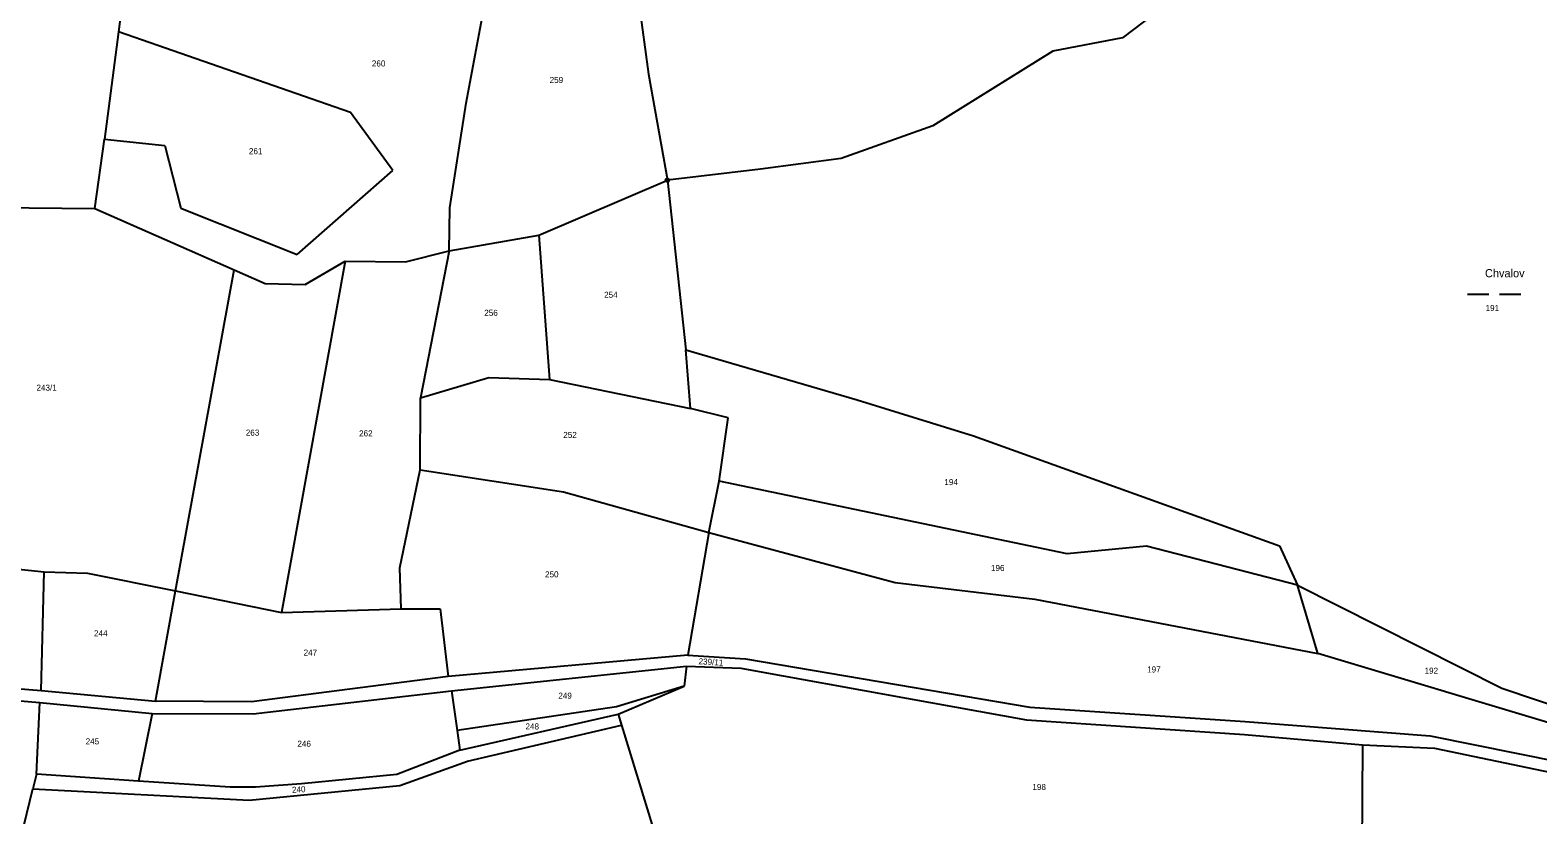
# Model space of a CAD drawing. Extents: x -794421 to -792735, y -1117671 to -1115559.
# Drawn here: x -794007.8 to -793585, y -1116101.2 to -1115881.2 of the extents above; entities that cross this region are included whole.
import ezdxf

# ---------------------------------------------------------------- set-up
doc = ezdxf.new("R2010")
doc.units = 0
for name, color, linetype in [('Vrstva 1', 7, 'Continuous'), ('Vrstva 14', 7, 'Continuous'), ('Vrstva 23', 7, 'Continuous'), ('Vrstva 28', 7, 'Continuous'), ('Vrstva 3', 7, 'Continuous'), ('Vrstva 44', 7, 'Continuous')]:
    doc.layers.add(name, color=color, linetype=linetype)

msp = doc.modelspace()

# ---------------------------------------------------------------- linework, layer by layer
at = {"layer": 'Vrstva 1'}
for p, q in [((-793981.74, -1115872.18), (-793982.97, -1115881.64)), ((-793885.49, -1115901.69), (-793881.05, -1115877.8)), ((-793982.97, -1115881.64), (-793986.9, -1115911.77)), ((-793917.95, -1115904.27), (-793982.97, -1115881.64)), ((-793906.06, -1115920.6), (-793917.95, -1115904.27)), ((-793890.06, -1115931.01), (-793885.49, -1115901.69)), ((-793989.67, -1115931.27), (-793986.9, -1115911.77)), ((-793986.9, -1115911.77), (-793969.98, -1115913.53)), ((-793969.98, -1115913.53), (-793965.54, -1115931.12)), ((-793932.88, -1115944.09), (-793906.06, -1115920.6)), ((-793865.09, -1115938.67), (-793829.08, -1115923.3)), ((-793829.08, -1115923.3), (-793823.91, -1115970.84)), ((-794038.38, -1115930.69), (-793989.67, -1115931.27)), ((-793989.67, -1115931.27), (-793950.58, -1115948.42)), ((-793965.54, -1115931.12), (-793932.88, -1115944.09)), ((-793890.28, -1115943.07), (-793890.06, -1115931.01)), ((-793890.28, -1115943.07), (-793865.09, -1115938.67)), ((-793865.09, -1115938.67), (-793862.1, -1115979.19)), ((-793919.41, -1115946.01), (-793937.25, -1116044.49)), ((-793930.65, -1115952.51), (-793919.41, -1115946.01)), ((-793919.41, -1115946.01), (-793902.53, -1115946.18)), ((-793902.53, -1115946.18), (-793890.28, -1115943.07)), ((-793890.28, -1115943.07), (-793898.31, -1115984.29)), ((-793967, -1116038.47), (-793950.58, -1115948.42)), ((-793950.58, -1115948.42), (-793941.85, -1115952.29)), ((-793941.85, -1115952.29), (-793930.65, -1115952.51)), ((-793823.91, -1115970.84), (-793775.82, -1115984.83)), ((-793822.57, -1115987.33), (-793823.91, -1115970.84)), ((-793898.31, -1115984.29), (-793879.15, -1115978.61)), ((-793879.15, -1115978.61), (-793862.1, -1115979.19)), ((-793862.1, -1115979.19), (-793822.57, -1115987.33)), ((-793898.42, -1116004.52), (-793898.31, -1115984.29)), ((-793775.82, -1115984.83), (-793743.24, -1115995)), ((-793812.03, -1115989.92), (-793822.57, -1115987.33)), ((-793814.59, -1116007.68), (-793812.03, -1115989.92)), ((-793743.24, -1115995), (-793657.44, -1116025.77)), ((-793904.1, -1116032), (-793898.42, -1116004.52)), ((-793898.42, -1116004.52), (-793858.22, -1116010.63)), ((-793817.49, -1116022.11), (-793814.59, -1116007.68)), ((-793716.97, -1116028.03), (-793814.59, -1116007.68)), ((-793858.22, -1116010.63), (-793817.49, -1116022.11)), ((-793817.49, -1116022.11), (-793823.34, -1116056.5)), ((-793817.49, -1116022.11), (-793765.24, -1116036.11)), ((-794059.95, -1116027.16), (-794003.8, -1116033.12)), ((-793694.7, -1116025.87), (-793716.97, -1116028.03)), ((-793652.4, -1116036.86), (-793694.7, -1116025.87)), ((-793657.44, -1116025.77), (-793652.4, -1116036.86)), ((-794004.72, -1116066.36), (-794003.8, -1116033.12)), ((-794003.8, -1116033.12), (-793991.65, -1116033.5)), ((-793991.65, -1116033.5), (-793967, -1116038.47)), ((-793903.72, -1116043.46), (-793904.1, -1116032)), ((-793972.59, -1116069.35), (-793967, -1116038.47)), ((-793967, -1116038.47), (-793937.25, -1116044.49)), ((-793765.24, -1116036.11), (-793726.06, -1116040.78)), ((-793652.4, -1116036.86), (-793595.03, -1116065.71)), ((-793646.63, -1116056.03), (-793652.4, -1116036.86)), ((-793937.25, -1116044.49), (-793903.72, -1116043.46)), ((-793903.72, -1116043.46), (-793892.8, -1116043.52)), ((-793892.8, -1116043.52), (-793890.53, -1116062.48)), ((-793726.06, -1116040.78), (-793646.63, -1116056.03)), ((-793823.34, -1116056.5), (-793890.53, -1116062.48)), ((-793823.34, -1116056.5), (-793807.18, -1116057.49)), ((-793568.92, -1116079.35), (-793646.63, -1116056.03)), ((-793889.59, -1116066.45), (-793823.74, -1116059.52)), ((-793823.74, -1116059.52), (-793824.33, -1116065.19)), ((-793823.74, -1116059.52), (-793808.47, -1116060.15)), ((-793808.47, -1116060.15), (-793762.05, -1116068.49)), ((-793807.18, -1116057.49), (-793727.4, -1116071.06)), ((-794065.04, -1116064.56), (-794005.06, -1116069.79)), ((-794064.7, -1116061.44), (-794004.72, -1116066.36)), ((-793890.53, -1116062.48), (-793945.69, -1116069.57)), ((-793824.33, -1116065.19), (-793843.38, -1116070.92)), ((-793842.87, -1116072.97), (-793824.33, -1116065.19)), ((-794005.99, -1116089.87), (-794005.06, -1116069.79)), ((-794005.06, -1116069.79), (-793973.59, -1116072.85)), ((-794004.72, -1116066.36), (-793972.59, -1116069.35)), ((-793945.69, -1116069.57), (-793972.59, -1116069.35)), ((-793945.24, -1116072.9), (-793889.59, -1116066.45)), ((-793889.59, -1116066.45), (-793887.99, -1116077.56)), ((-793762.05, -1116068.49), (-793728.37, -1116074.65)), ((-793595.03, -1116065.71), (-793554.97, -1116079.2)), ((-793973.59, -1116072.85), (-793977.38, -1116091.77)), ((-793973.59, -1116072.85), (-793945.24, -1116072.9)), ((-793843.38, -1116070.92), (-793887.99, -1116077.56)), ((-793887.23, -1116083.12), (-793842.87, -1116072.97)), ((-793842.87, -1116072.97), (-793841.9, -1116076.14)), ((-793727.4, -1116071.06), (-793667.04, -1116075.09)), ((-793887.99, -1116077.56), (-793887.23, -1116083.12)), ((-793885.12, -1116086.22), (-793841.9, -1116076.14)), ((-793841.9, -1116076.14), (-793832.93, -1116105.39)), ((-793728.37, -1116074.65), (-793667.23, -1116078.69)), ((-793667.04, -1116075.09), (-793615.17, -1116079.08)), ((-793667.23, -1116078.69), (-793634.16, -1116081.65)), ((-793634.16, -1116081.65), (-793634.36, -1116123.68)), ((-793634.16, -1116081.65), (-793613.99, -1116082.51)), ((-793615.17, -1116079.08), (-793578.57, -1116086.49)), ((-793887.23, -1116083.12), (-793904.98, -1116089.91)), ((-793904.06, -1116092.99), (-793885.12, -1116086.22)), ((-793613.99, -1116082.51), (-793581.25, -1116089.41)), ((-794005.99, -1116089.87), (-794006.98, -1116093.99)), ((-793977.38, -1116091.77), (-794005.99, -1116089.87)), ((-793904.98, -1116089.91), (-793931.71, -1116092.54)), ((-794032.68, -1116198.52), (-794006.98, -1116093.99)), ((-794006.98, -1116093.99), (-793946.39, -1116097.1)), ((-793951.68, -1116093.47), (-793977.38, -1116091.77)), ((-793944.54, -1116093.53), (-793951.68, -1116093.47)), ((-793946.39, -1116097.1), (-793904.06, -1116092.99)), ((-793931.71, -1116092.54), (-793944.54, -1116093.53))]:
    msp.add_line(p, q, dxfattribs=at)
at = {"layer": 'Vrstva 23'}
for p, q in [((-793604.7, -1115955.29), (-793598.7, -1115955.29)), ((-793595.7, -1115955.29), (-793589.7, -1115955.29))]:
    msp.add_line(p, q, dxfattribs=at)
at = {"layer": 'Vrstva 28'}
for radius in [0.5, 0.01]:
    msp.add_circle((-793829.08, -1115923.3), radius, dxfattribs=at)
at = {"layer": 'Vrstva 3'}
for p, q in [((-793837.04, -1115873.54), (-793834.39, -1115893.52)), ((-793686.79, -1115872.11), (-793701.42, -1115883.35)), ((-793701.42, -1115883.35), (-793720.98, -1115887.13)), ((-793720.98, -1115887.13), (-793754.63, -1115908.05)), ((-793834.39, -1115893.52), (-793829.08, -1115923.3)), ((-793754.63, -1115908.05), (-793780.31, -1115917.18)), ((-793780.31, -1115917.18), (-793802.92, -1115920.15)), ((-793802.92, -1115920.15), (-793829.08, -1115923.3))]:
    msp.add_line(p, q, dxfattribs=at)

# ---------------------------------------------------------------- texts
at = {"layer": 'Vrstva 14'}
for s, p in [('260', (-793911.936, -1115891.4)), ('259', (-793862.093, -1115896.03)), ('261', (-793946.42, -1115915.99)), ('254', (-793846.819, -1115956.27)), ('256', (-793880.423, -1115961.33)), ('191', (-793599.633, -1115959.97)), ('243/1', (-794005.989, -1115982.31)), ('263', (-793947.297, -1115994.92)), ('262', (-793915.526, -1115995.12)), ('252', (-793858.273, -1115995.57)), ('194', (-793751.396, -1116008.79)), ('196', (-793738.33, -1116032.87)), ('250', (-793863.382, -1116034.65)), ('244', (-793989.858, -1116051.18)), ('247', (-793931.079, -1116056.6)), ('197', (-793694.537, -1116061.33)), ('192', (-793616.74, -1116061.68)), ('249', (-793859.652, -1116068.67)), ('248', (-793868.862, -1116077.31)), ('245', (-793992.209, -1116081.48)), ('246', (-793932.822, -1116082.14)), ('198', (-793726.71, -1116094.28))]:
    msp.add_text(s, height=1.7, dxfattribs=at).set_placement(p)
for s, rotation, p in [('239/11', 356.32899, (-793820.368, -1116058.998)), ('240', 3.35907, (-793934.288, -1116095.097))]:
    msp.add_text(s, height=1.7, rotation=rotation, dxfattribs=at).set_placement(p)
at = {"layer": 'Vrstva 44'}
msp.add_text('Chvalov', height=2.3, dxfattribs=at).set_placement((-793599.8, -1115950.51))

doc.saveas('drawing.dxf')
